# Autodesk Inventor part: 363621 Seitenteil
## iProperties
Created: 2006-06
Part Number: 363621 Seitenteil
Material: 1.0330.5
Document SubType Name: Sheet Metal
Designer: I.Baliuc
Manufacturer: Standard
Standards Organization: Custom
Description: Seitenblech, links
Cost Center: 1,987 kg
Authority: 253384 mm^3
Density: 7.84 g/cm^3
Sheet Metal Rule: Standard
Title: Seitenblech, links
Company: Mayer & Müller AG Schaltgeräte
HalbzeugNorm: DIN 1544
Zweck: Vorkontakt HSLT
SaveDate: 2006-11-02
SaveTime: 21:17
TotalMass: 1,987 kg
TotalVolume: 253384 mm^3
SM_Thickness: 3 mm
SM_Style: Standard
SM_Extents: N/A
SM_Extents_Width: 0,00 mm
SM_Extents_Length: 0,00 mm
Author: T.Messerschmitt
Revision Number: 363621
Keywords: 363031
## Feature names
1. Bohrung_Ø5 [Hole]
2. Bohrung_Ø10 [Hole]
3. Bohrung_Ø55 [Hole]
4. Extrusion8
5. Bohrung25 [Hole]
6. Neue Bohrung26 [Hole]
7. Rechteckige Anordnung4 [Rectangular Pattern]
8. Bohrung_Ø8.5_01 [Hole]
9. Bohrung_Ø8.5_02 [Hole]
10. Bohrung_Ø8.5_03 [Hole]
11. Bohrung_Ø8.5_04 [Hole]
12. Bezeichnung2 [Tagging]
13. Grobblech9
14. Biegung8
15. Ausschneiden6
16. Ausschneiden8
17. Ausschneiden9
